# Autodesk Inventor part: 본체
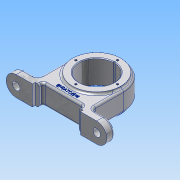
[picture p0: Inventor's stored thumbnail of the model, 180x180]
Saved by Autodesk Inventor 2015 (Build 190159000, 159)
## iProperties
Created: 2019-05
Part Number: 본체
Material: 알루미늄 6061
Document SubType Name: Modeling
Designer: user
Density: 2.7 g/cm^3
Appearance: 알루미늄 - 평지
Author: user
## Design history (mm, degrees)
sketch "스케치1"
  geometry: L1 (75, -15)-(-75, -15); L2 (-75, -15)-(-75, 15); L3 (-75, 15)-(75, 15); L4 (75, 15)-(75, -15); L5 (75, -15)-(-75, 15); L6 (-75, -15)-(75, 15); 1 further point
  constraints: 12 end point, 2 midpoint, 2 parallel, 1 horizontal, 1 perpendicular
  dimensions: "d0" = 150 distance of L2.end L3.end; "d1" = 30 distance of L1.end L2.end
extrude "돌출1" new body sketch "스케치1" distance "d2" = 12; taper "d3" = 0 deg
fillet "모깎기1" dims "d4" = 15
sketch "스케치2"
  geometry: L1 (60, 15)-(-60, 15) reference; L2 (36, -15)-(-36, -15); L3 (-36, -15)-(-36, 15); L4 (-36, 15)-(36, 15); L5 (36, 15)-(36, -15); L6 (36, -15)-(-36, 15); L7 (-36, -15)-(36, 15); 1 further point
  constraints: 12 end point, 2 midpoint, 2 parallel, 1 horizontal, 1 perpendicular, 1 point on line
  dimensions: "d5" = 72 distance of L3.end L4.end
extrude "돌출2" cut sketch "스케치2" distance "d6" = 4; taper "d7" = 0 deg
sketch "스케치3"
  geometry: L1 (-36, 15)-(36, 15) reference; L2 (30, -15)-(-30, -15); L3 (-30, -15)-(-30, 15); L4 (-30, 15)-(30, 15); L5 (30, 15)-(30, -15); L6 (30, -15)-(-30, 15); L7 (-30, -15)-(30, 15); 1 further point
  constraints: 12 end point, 2 midpoint, 2 parallel, 1 horizontal, 1 perpendicular, 1 point on line
  dimensions: "d8" = 60 distance of L3.end L4.end
extrude "돌출3" cut sketch "스케치3" distance "d9" = 6; taper "d10" = 0 deg
node "작업 평면1"
node "작업 평면2"
sketch "스케치10"
  geometry: C1 r 9 at (-60, 0); C2 r 9 at (60, 0); A1 r 15 centre (-60, 0) between (-60, 15) and (-60, -15) reference; A2 r 15 centre (60, 0) between (60, -15) and (60, 15) reference; 1 further point
  constraints: 2 centre point, 2 coincident
  dimensions: "d22" = 18 diameter of C1; "d23" = 18 diameter of C2
extrude "돌출8" join sketch "스케치10" distance "d24" = 3; taper "d25" = 0 deg
sketch "스케치11"
  geometry: C1 r 9 at (0, 0) reference; A1 r 15 centre (120, 0) between (120, -15) and (120, 15) reference; 3 further points
  constraints: 2 coincident
hole "구멍1" sketch "스케치11" at (0, 0), (120, 0) diameter "d26" = 11; stored, may be unused: countersink angle "d30" = 90 deg, drill point angle "d32" = 118 deg; dims "d27" = 6, "d28" = 4, "d29" = 2, "d31" = 8
fillet "모깎기4" dims "d66" = 3
fillet "모깎기5" dims "d67" = 3
node "작업 평면7"
sketch "스케치18"
  geometry: C1 r 40 at (60, 60); 1 further point
  constraints: 1 centre point
  dimensions: "d72" = 40 radius of C1; "d73" = 60 distance of point (60, 0) C1.centre
extrude "돌출10" join sketch "스케치18" stored distance "d74" = 30; taper "d75" = 0 deg
sketch "스케치19"
  geometry: C1 r 40 at (0, 0) reference; C2 r 36 at (0, 0); 1 further point
  constraints: 1 centre point, 1 coincident
  dimensions: "d76" = 72 diameter of C2
extrude "돌출11" join sketch "스케치19" distance "d77" = 3; taper "d78" = 0 deg
sketch "스케치20"
  geometry: C1 r 40 at (0, 0) reference; C2 r 36 at (0, 0); 1 further point
  constraints: 1 centre point, 1 coincident
  dimensions: "d79" = 72 diameter of C2
extrude "돌출12" join sketch "스케치20" distance "d80" = 3; taper "d81" = 0 deg
node "작업 평면8"
sketch "스케치21"
  geometry: L1 (20, 60)-(20, 11.494); L2 (100, 60)-(100, 11.494); L3 (20, 11.494)-(100, 11.494); A1 r 40 centre (60, 60) between (100, 60) and (20, 60) reference; 1 further point
  constraints: 6 end point, 2 point on circle, 2 tangent, 2 vertical, 1 perpendicular
extrude "돌출13" join sketch "스케치21" stored distance "d82" = 30; taper "d83" = 0 deg
hole "구멍5" diameter "d86" = 52; stored, may be unused: countersink angle "d90" = 90 deg, drill point angle "d92" = 0 deg; dims "d84" = 10, "d85" = 10, "d87" = 8, "d88" = 7, "d89" = 1, "d91" = 10
sketch "스케치22"
  geometry: 3 further points
  constraints: 1 vertical alignment, 1 other
hole "구멍6" sketch "스케치22" at (0, 26) diameter "d93" = 3; stored, may be unused: countersink angle "d97" = 90 deg, drill point angle "d99" = 0 deg; dims "d94" = 8, "d95" = 7, "d96" = 1, "d98" = 10
node "작업 평면9"
sketch "스케치23"
  geometry: 2 further points
  constraints: 1 coincident
hole "구멍7" sketch "스케치23" at (0, 0) diameter "d100" = 4.917; stored, may be unused: countersink angle "d104" = 90 deg, drill point angle "d106" = 118 deg; dims "d101" = 8, "d102" = 7, "d103" = 1, "d105" = 10
node "작업 평면11"
  node "작업 평면10"
sketch "스케치24"
  geometry: C1 r 1 at (0, 165.837); 1 further point
  constraints: 1 centre point, 1 coincident
  dimensions: "d108" = 2 diameter of C1
extrude "돌출14" cut sketch "스케치24" distance "d109" = 30; taper "d110" = 0 deg
sketch "스케치25" dims "d111" = 62
  geometry: C1 r 36 at (0, 0) reference; 3 further points
  constraints: 1 coincident, 1 vertical alignment, 2 other
hole "구멍8" sketch "스케치25" at (0, 31) diameter "d112" = 3.242; stored, may be unused: countersink angle "d116" = 90 deg, drill point angle "d118" = 118 deg; dims "d113" = 6, "d114" = 7, "d115" = 1, "d117" = 8
node "작업 평면12"
fillet "모깎기7" dims "d122" = 6
fillet "모깎기8" dims "d123" = 3
fillet "모깎기9" dims "d124" = 3
fillet "모깎기10" dims "d125" = 3
chamfer "모따기2" distance "d126" = 1; stored, may be unused: second distance "d127" = 2, angle "d128" = 45 deg
sketch "스케치26"
  geometry: L1 (33, 10)-(87, 10) reference; A1 r 39 centre (60, 60) between (23, 47.671) and (97, 47.671) reference; 2 further points
  constraints: 1 vertical alignment, 1 other
  dimensions: "d129" = 7 distance from line of point (60, 17) L1
extrude "돌출15" join sketch "스케치26" distance "d130" = 0.5; taper "d131" = 0 deg
node "솔리드1"
pattern_circular "원형 패턴2" dims angle "d120" = 360 deg
mirror "대칭2"
other parameters: "d107" = -2.75
